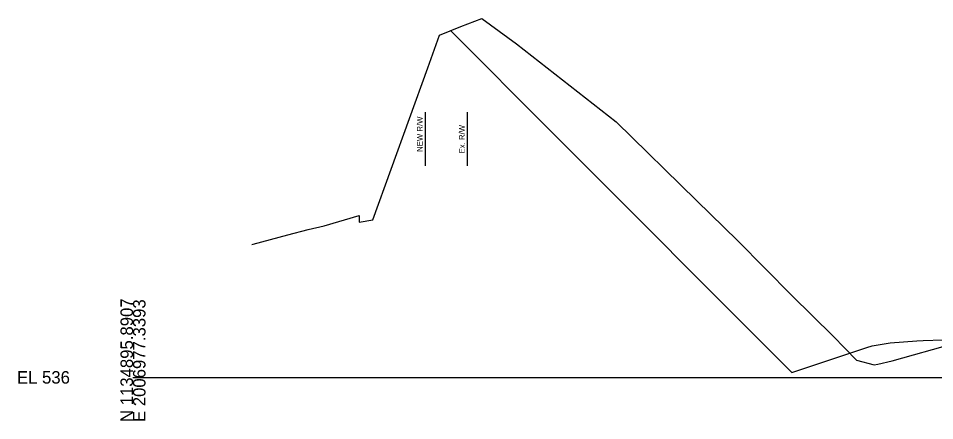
# Model space of a CAD drawing. Extents: x -201 to 2007062, y -213 to 1139737.
# Drawn here: x 974.3 to 1179.6, y 1490.3 to 1580.4 of the extents above; entities that cross this region are included whole.
import ezdxf

# ---------------------------------------------------------------- set-up
doc = ezdxf.new("R2010")
doc.units = 0
for name, color, linetype in [('Default', 7, 'Continuous'), ('RD_DTM_Design_FG', 7, 'Continuous'), ('RD_GPK_XS_Cell', 7, 'Continuous'), ('RD_XS_ExGround', 7, 'Continuous'), ('RD_XS_ExRW', 7, 'Continuous'), ('RD_XS_NewRW', 7, 'Continuous')]:
    doc.layers.add(name, color=color, linetype=linetype)

msp = doc.modelspace()

# ---------------------------------------------------------------- linework, layer by layer
at = {"layer": 'RD_DTM_Design_FG'}
msp.add_lwpolyline([(1071.19, 1577.63), (1093.72, 1555.08), (1147.64, 1501.11), (1164.42, 1506.67), (1165.65, 1507.08), (1169.65, 1507.72), (1175.66, 1508.19), (1177.06, 1508.24), (1185.83, 1508.58), (1191.63, 1508.8), (1191.67, 1508.8), (1196, 1509.14)], dxfattribs=at)
at = {"layer": 'RD_GPK_XS_Cell'}
msp.add_line((1000, 1500), (1250, 1500), dxfattribs=at)
at = {"layer": 'RD_XS_ExGround'}
msp.add_lwpolyline([(1026.6, 1529.73), (1026.92, 1529.81), (1030.78, 1530.85), (1034.67, 1531.89), (1039.26, 1533.12), (1042.86, 1533.91), (1050.68, 1536.22), (1050.68, 1534.73), (1053.73, 1535.25), (1066.05, 1569.33), (1068.7, 1576.6), (1073.42, 1578.6), (1078.19, 1580.4), (1085.94, 1574.73), (1108.26, 1557.19), (1126.28, 1539.6), (1135.52, 1530.58), (1147.62, 1518.31), (1156.87, 1509.2), (1162.08, 1503.82), (1166.07, 1502.79), (1166.89, 1502.96), (1170.08, 1503.72), (1183.95, 1507.61)], dxfattribs=at)
at = {"layer": 'RD_XS_ExRW'}
msp.add_line((1074.85, 1559.39), (1074.85, 1547.39), dxfattribs=at)
at = {"layer": 'RD_XS_NewRW'}
msp.add_line((1065.45, 1559.39), (1065.45, 1547.39), dxfattribs=at)

# ---------------------------------------------------------------- texts
at = {"layer": 'Default'}
msp.add_text('-', height=0.0001, dxfattribs=at).set_placement((1000, 1500))
at = {"layer": 'RD_GPK_XS_Cell'}
for s, p in [('N 1134895.8907', (1000, 1490)), ('E 2006977.3393', (1002.8, 1490))]:
    msp.add_text(s, height=2.8, rotation=90, dxfattribs=at).set_placement(p)
msp.add_text('EL 536', height=2.8, dxfattribs=at).set_placement((974, 1498.6))
at = {"layer": 'RD_XS_ExRW'}
msp.add_text('Ex. R/W ', height=1.3, rotation=90, dxfattribs=at).set_placement((1074.35, 1550.15))
at = {"layer": 'RD_XS_NewRW'}
msp.add_text('NEW R/W ', height=1.3, rotation=90, dxfattribs=at).set_placement((1064.92, 1550.5))

doc.saveas('drawing.dxf')
